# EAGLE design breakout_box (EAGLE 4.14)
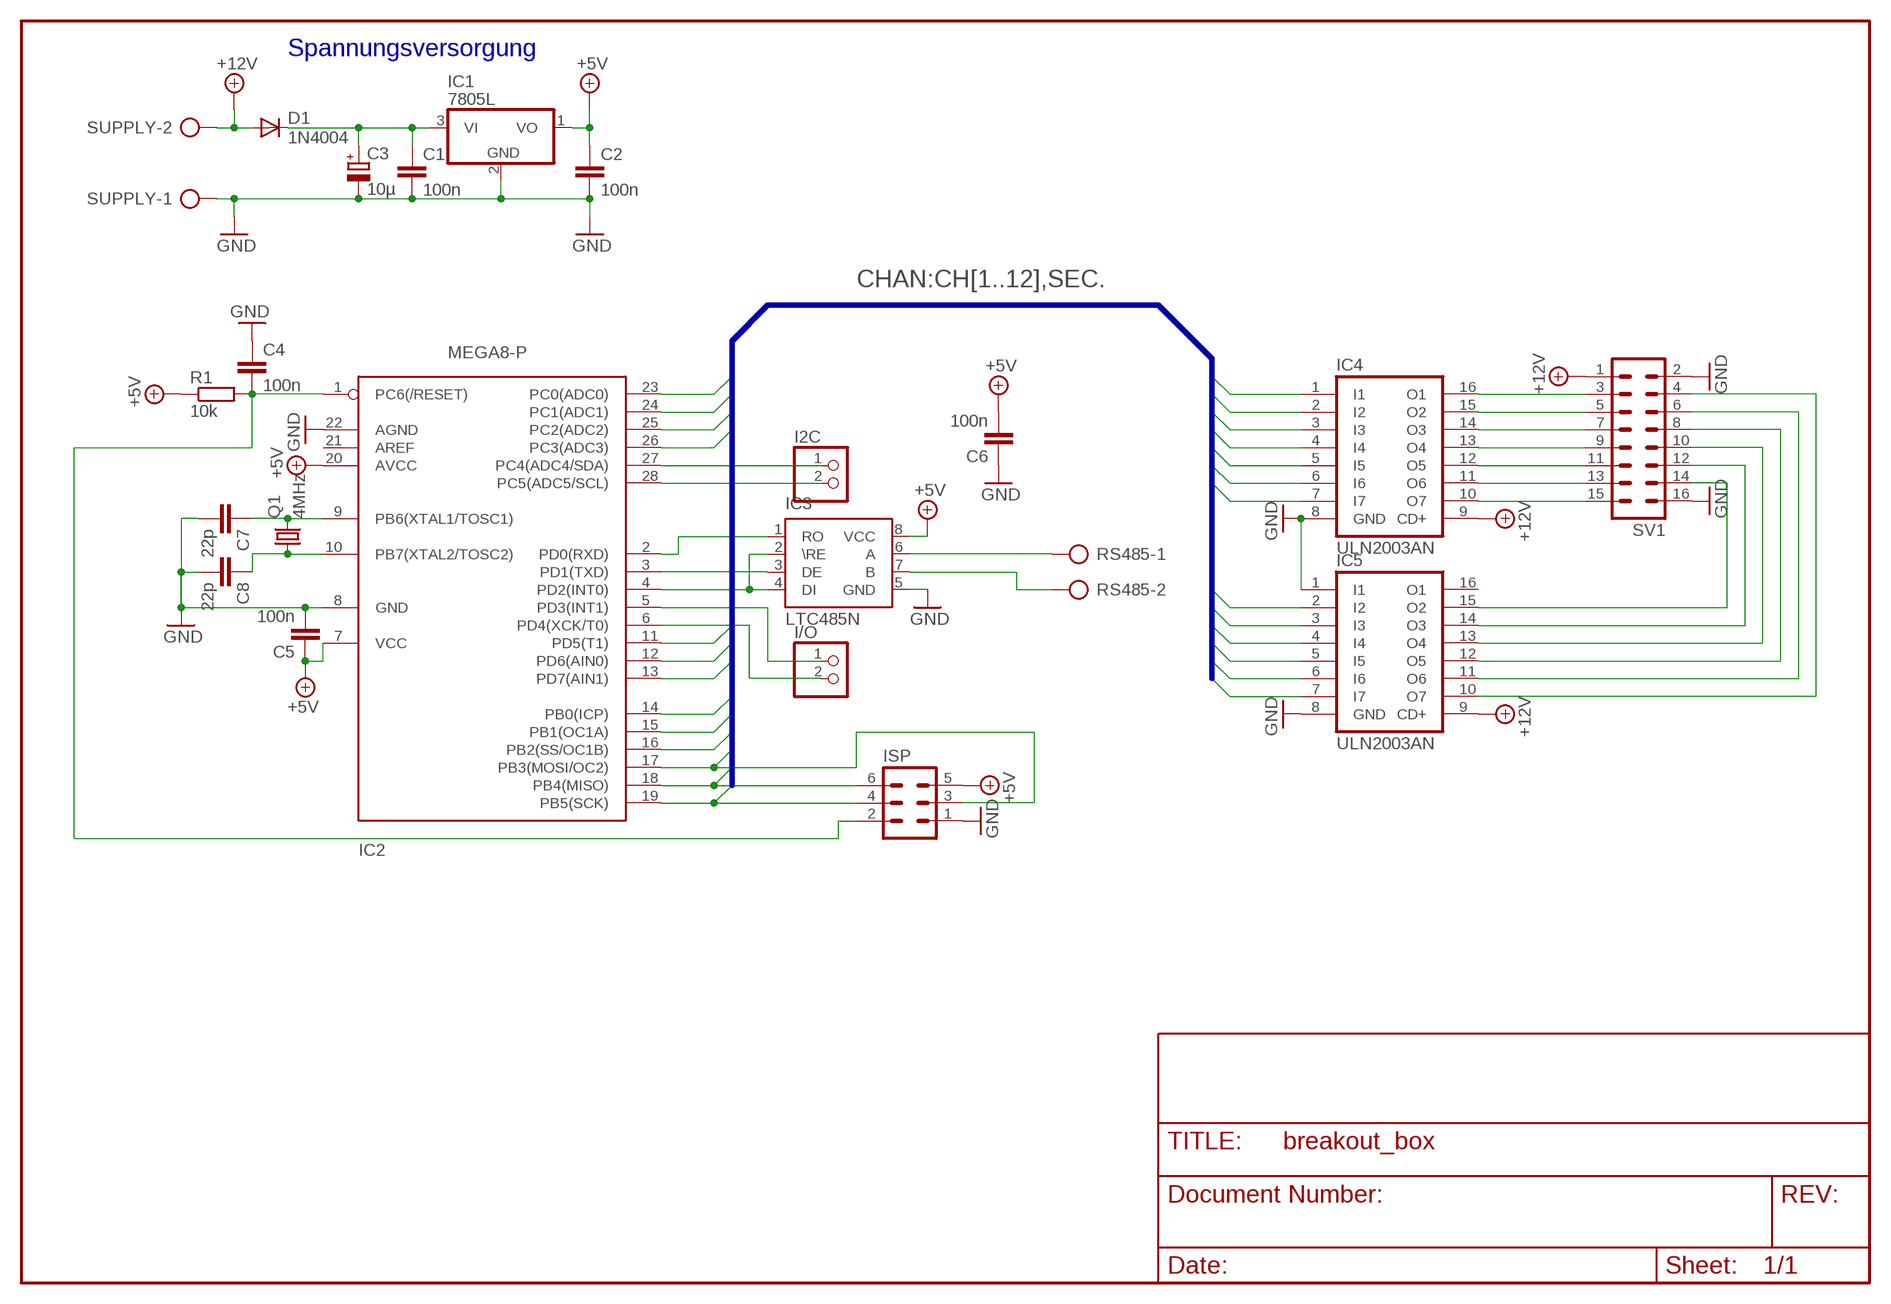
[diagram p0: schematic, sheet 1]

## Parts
C1  100n  C-EU025-024X044  [C025-024X044]
C2  100n  C-EU025-024X044  [C025-024X044]
C3  10µ  CPOL-EUE2-5  [E2-5]
C4  100n  C-EU025-024X044  [C025-024X044]
C5  100n  C-EU025-024X044  [C025-024X044]
C6  100n  C-EU025-024X044  [C025-024X044]
C7  22p  C-EU025-024X044  [C025-024X044]
C8  22p  C-EU025-024X044  [C025-024X044]
D1  1N4004  [DO41-10]
I2C  PINHD-1X2  [1X02]
I/O  PINHD-1X2  [1X02]
IC1  7805L  [TO92]
IC2  MEGA8-P  [DIL28-3]
IC3  LTC485N  [DIL08]
IC4  ULN2003AN  [DIL16]
IC5  ULN2003AN  [DIL16]
ISP  ML6  [ML6]
Q1  4MHz  CRYTALHC49U-V  [HC49U-V]
R1  10k  R-EU_0207/10  [0207/10]
RS485  AK500/2  [AK500/2]
SUPPLY  AK500/2  [AK500/2]
SV1  ML16  [ML16]

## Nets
+5V: C2.1 C5.1 C6.2 IC1.1(VO) IC2.7(VCC) IC2.20(AVCC) IC3.8(VCC) ISP.5 R1.1
+12V: D1.A IC4.9(CD+) IC5.9(CD+) SUPPLY.2 SV1.1
CH1: IC2.26(PC3(ADC3)) IC4.1(I1)
CH2: IC2.25(PC2(ADC2)) IC4.2(I2)
CH3: IC2.24(PC1(ADC1)) IC4.3(I3)
CH4: IC2.19(PB5(SCK)) IC4.4(I4) ISP.4
CH5: IC2.18(PB4(MISO)) IC4.5(I5) ISP.6
CH6: IC2.17(PB3(MOSI/OC2)) IC4.6(I6) ISP.3
CH7: IC2.16(PB2(SS/OC1B)) IC4.7(I7)
CH8: IC2.15(PB1(OC1A)) IC5.3(I3)
CH9: IC2.14(PB0(ICP)) IC5.4(I4)
CH10: IC2.13(PD7(AIN1)) IC5.5(I5)
CH11: IC2.12(PD6(AIN0)) IC5.6(I6)
CH12: IC2.11(PD5(T1)) IC5.7(I7)
GND: C1.2 C2.2 C3.- C4.1 C5.2 C6.1 C7.2 C8.2 IC1.2(GND) IC2.8(GND) IC2.22(AGND) IC3.5(GND) IC4.8(GND) IC5.1(I1) IC5.8(GND) ISP.1 SUPPLY.1 SV1.2 SV1.16
N$1: IC3.7(B) RS485.2
N$2: IC3.6(A) RS485.1
N$3: IC2.2(PD0(RXD)) IC3.1(RO)
N$4: IC2.3(PD1(TXD)) IC3.3(DE)
N$5: IC4.16(O1) SV1.3
N$6: I/O.1 IC2.5(PD3(INT1))
N$7: IC4.15(O2) SV1.5
N$8: I2C.1 IC2.27(PC4(ADC4/SDA))
N$9: I2C.2 IC2.28(PC5(ADC5/SCL))
N$10: C7.1 IC2.9(PB6(XTAL1/TOSC1)) Q1.2
N$11: C1.1 C3.+ D1.C IC1.3(VI)
N$12: IC4.14(O3) SV1.7
N$13: IC4.13(O4) SV1.9
N$14: IC4.12(O5) SV1.11
N$15: IC4.11(O6) SV1.13
N$16: IC4.10(O7) SV1.15
N$17: IC5.15(O2) SV1.14
N$18: I/O.2 IC2.6(PD4(XCK/T0))
N$19: IC5.14(O3) SV1.12
N$20: IC5.13(O4) SV1.10
N$21: IC5.12(O5) SV1.8
N$22: IC5.11(O6) SV1.6
N$23: IC5.10(O7) SV1.4
N$24: C8.1 IC2.10(PB7(XTAL2/TOSC2)) Q1.1
N$25: IC2.4(PD2(INT0)) IC3.2(\RE) IC3.4(DI)
RESET: C4.2 IC2.1(PC6(/RESET)) ISP.2 R1.2
SEC.: IC2.23(PC0(ADC0)) IC5.2(I2)
Unconnected: IC2.21(AREF) IC5.16(O1)

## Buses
CHAN:CH[1..12],SEC.

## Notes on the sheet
- Spannungsversorgung

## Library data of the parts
C1 C2 C4-C8 = rcl:C-EU: CAPACITOR, European symbol
C3 = rcl:CPOL-EU: POLARIZED CAPACITOR, European symbol
D1 = diode:1N4004: DIODE
I2C I/O = pinhead:PINHD-1X2: PIN HEADER
IC1 = linear:78*: Positive VOLTAGE REGULATOR Source: http://cache.national.com/ds/LM/LM78L05.pdf http://www.fairchildsemi.com/ds/LM/LM7805.pdf
IC2 = atmel:MEGA8-P: MICROCONTROLLER 8 Kbytes FLASH 1 kbytes SRAM 512 bytes EEPROM USART 4-channel 10 bit ADC 2-channel 8 bit ADC Source: avr.lbr
IC3 = linear-technology:LTC485: Low Power RS485 Interface Transceiver Source: http://www.linear.com/pc/downloadDocument.do?navId=H0,C1,C1007,C1017,P2064,D1718
IC4 IC5 = uln-udn:ULN2003A: DRIVER ARRAY
ISP = con-harting-ml:ML6: HARTING
Q1 = crystal:CRYTAL: CRYSTAL
R1 = rcl:R-EU_: RESISTOR, European symbol
RS485 SUPPLY = con-ptr500:AK500/2: CONNECTOR
SV1 = con-harting-ml:ML16: HARTING

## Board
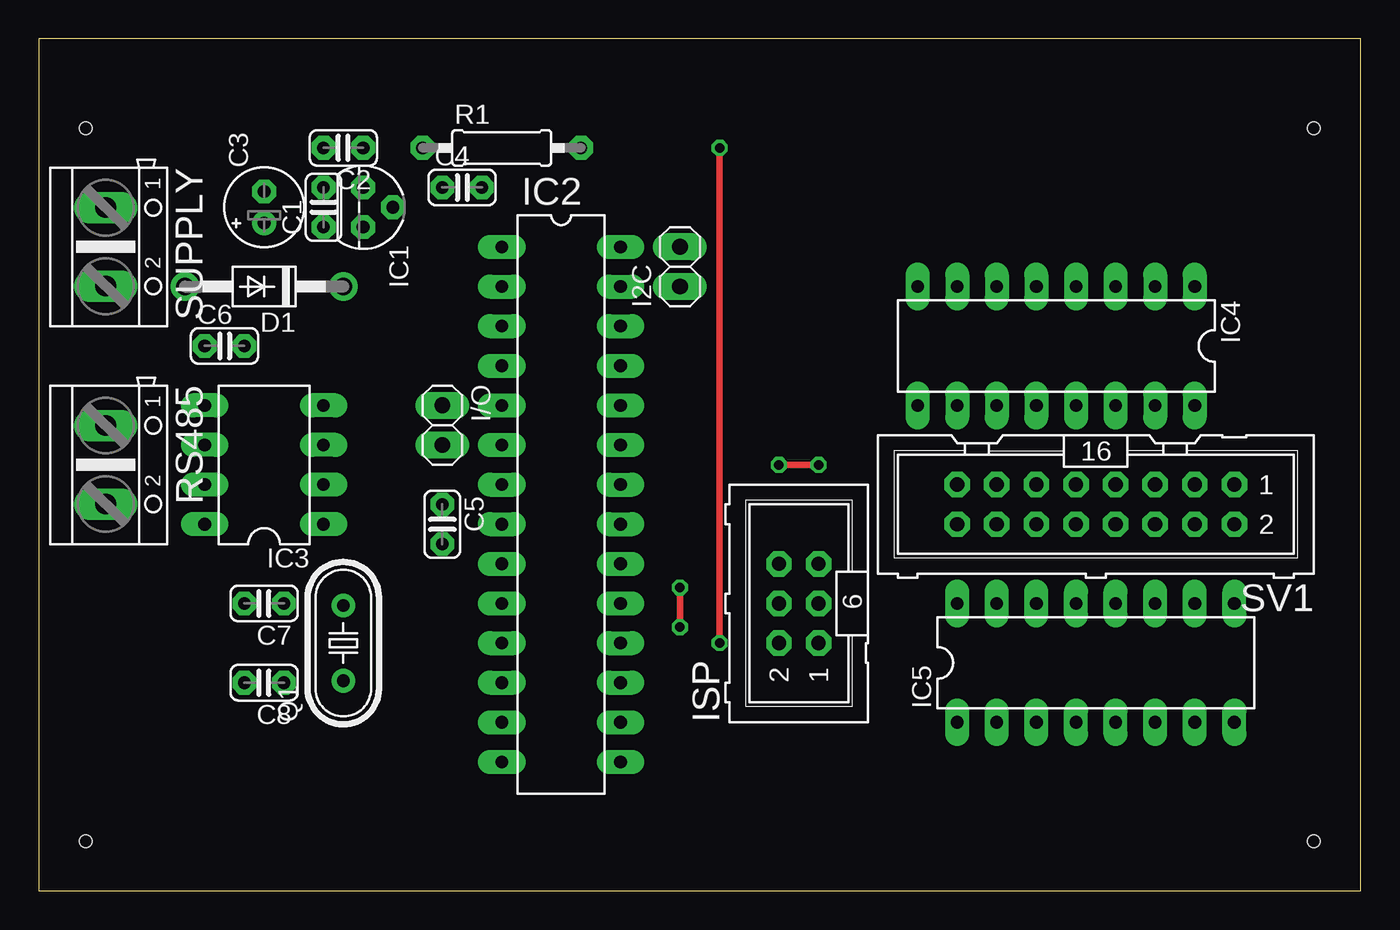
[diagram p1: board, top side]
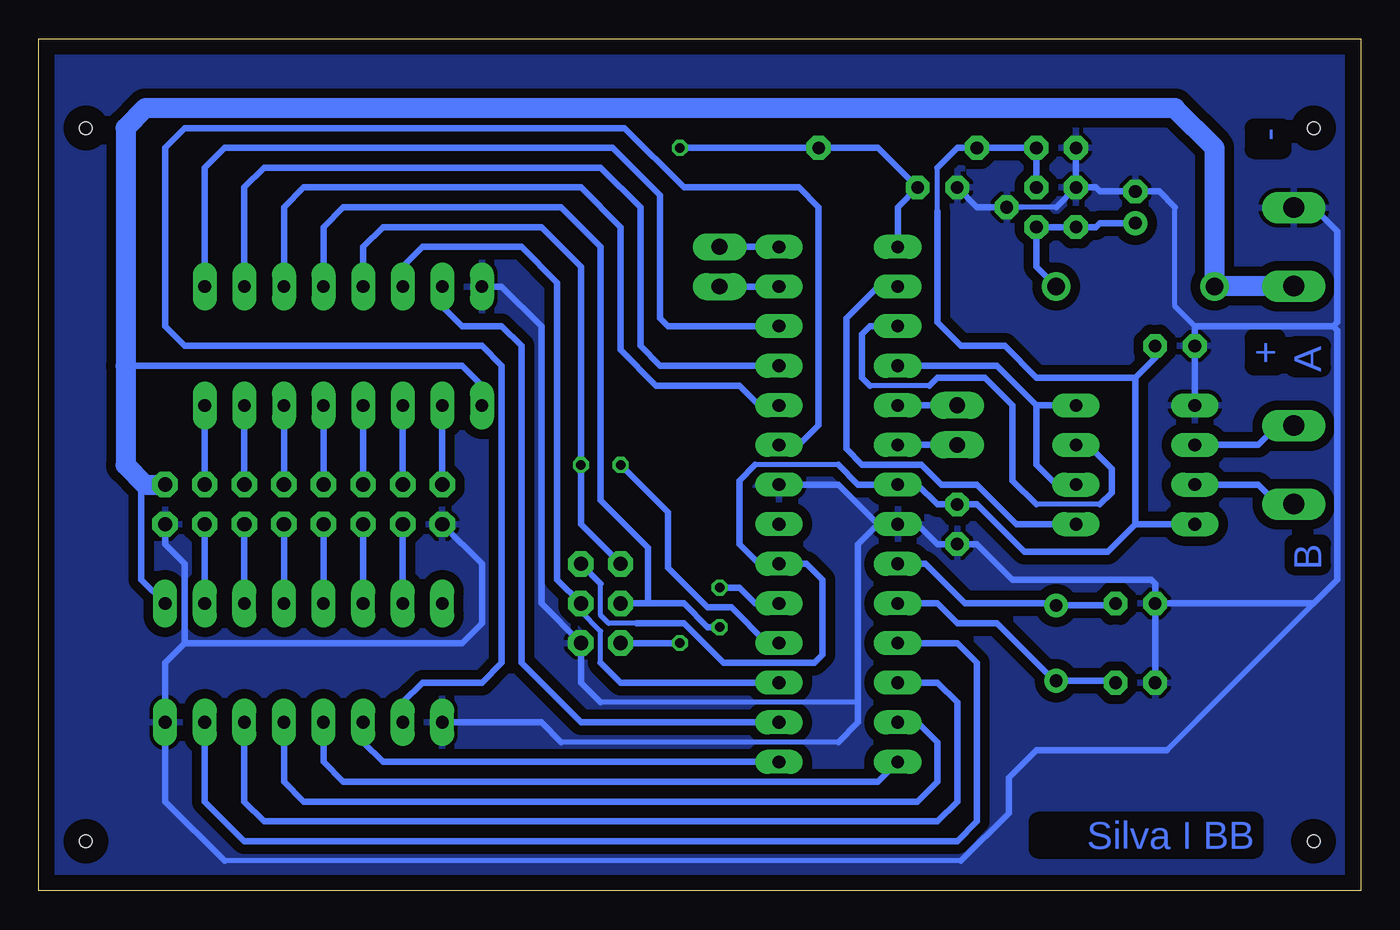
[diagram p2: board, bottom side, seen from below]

Size 84.76 x 54.6 mm. Coordinates in mm from the lower left corner, seen from the top.
Outline: 0,0 84.76,0 84.76,54.6 0,54.6 0,0
Copper layers (1*16): Top 0.035mm / dielectric 1.5mm / Bottom 0.035mm
Design rules "default": minimum track width 12mil, minimum drill 24mil, track to track 12mil, track to pad 12mil, pad to pad 12mil, via to via 12mil, smd to smd 8mil, copper to edge 40mil, drill to drill 8mil, minimum pad ring 14mil, minimum via ring 8mil, stop-mask expansion 4mil, vias tented up to drill 0mil, thermal gap 10mil
Holes 0.8 mm at 81.75,48.89 81.75,3.17 3.01,48.89 3.01,3.17

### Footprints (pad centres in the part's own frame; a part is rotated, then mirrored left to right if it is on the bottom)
C025-024X044 = drill 0.813 octagon: 1 -1.27,0; 2 1.27,0
E2-5 = drill 0.813 pad 1.27 round: + -1.016,0 | drill 0.813 pad 1.27 octagon: - 1.016,0
DO41-10 = drill 1.118 round: A 5.08,0; C -5.08,0
1X02 = drill 1.016 long: 1 -1.27,0; 2 1.27,0
TO92 = drill 0.813 octagon: 1 -1.27,0; 2 0,1.905; 3 1.27,0
DIL28-3 = drill 0.813 long: 1 -16.51,-3.81; 2 -13.97,-3.81; 3 -11.43,-3.81; 4 -8.89,-3.81; 5 -6.35,-3.81; 6 -3.81,-3.81; 7 -1.27,-3.81; 8 1.27,-3.81; 9 3.81,-3.81; 10 6.35,-3.81; 11 8.89,-3.81; 12 11.43,-3.81; 13 13.97,-3.81; 14 16.51,-3.81; 15 16.51,3.81; 16 13.97,3.81; 17 11.43,3.81; 18 8.89,3.81; 19 6.35,3.81; 20 3.81,3.81; 21 1.27,3.81; 22 -1.27,3.81; 23 -3.81,3.81; 24 -6.35,3.81; 25 -8.89,3.81; 26 -11.43,3.81; 27 -13.97,3.81; 28 -16.51,3.81
DIL08 = drill 0.813 long: 1 -3.81,-3.81; 2 -1.27,-3.81; 3 1.27,-3.81; 4 3.81,-3.81; 5 3.81,3.81; 6 1.27,3.81; 7 -1.27,3.81; 8 -3.81,3.81
DIL16 = drill 0.813 long: 1 -8.89,-3.81; 2 -6.35,-3.81; 3 -3.81,-3.81; 4 -1.27,-3.81; 5 1.27,-3.81; 6 3.81,-3.81; 7 6.35,-3.81; 8 8.89,-3.81; 9 8.89,3.81; 10 6.35,3.81; 11 3.81,3.81; 12 1.27,3.81; 13 -1.27,3.81; 14 -3.81,3.81; 15 -6.35,3.81; 16 -8.89,3.81
ML6 = drill 0.914 octagon: 1 -2.54,-1.27; 2 -2.54,1.27; 3 0,-1.27; 4 0,1.27; 5 2.54,-1.27; 6 2.54,1.27
HC49U-V = drill 0.813 round: 1 -2.413,0; 2 2.413,0
0207/10 = drill 0.813 octagon: 1 -5.08,0; 2 5.08,0
AK500/2 = drill 1.321 long: 1 -2.515,0; 2 2.515,0
ML16 = drill 0.914 octagon: 1 -8.89,-1.27; 2 -8.89,1.27; 3 -6.35,-1.27; 4 -6.35,1.27; 5 -3.81,-1.27; 6 -3.81,1.27; 7 -1.27,-1.27; 8 -1.27,1.27; 9 1.27,-1.27; 10 1.27,1.27; 11 3.81,-1.27; 12 3.81,1.27; 13 6.35,-1.27; 14 6.35,1.27; 15 8.89,-1.27; 16 8.89,1.27

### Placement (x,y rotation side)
C1  18.25,43.81 90 top
C2  19.52,47.62 180 top
C3  14.44,43.81 90 top
C4  27.14,45.08 0 top
C5  25.87,23.49 270 top
C6  11.9,34.92 0 top
C7  14.44,18.41 180 top
C8  14.44,13.33 180 top
D1  14.44,38.73 180 top
I2C  41.11,40 90 top
I/O  25.87,29.84 270 top
IC1  20.79,43.81 270 top
IC2  33.49,24.76 270 top
IC3  14.44,27.3 90 top
IC4  65.24,34.92 180 top
IC5  67.78,14.6 0 top
ISP  48.73,18.41 90 top
Q1  19.52,15.87 90 top
R1  29.68,47.62 0 top
RS485  4.28,27.3 270 top
SUPPLY  4.28,41.27 270 top
SV1  67.78,24.76 180 top

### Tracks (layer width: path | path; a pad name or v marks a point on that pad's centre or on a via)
+5V
  Bottom 0.305: 27.14,43.56 27.14,46.35 | IC3.8 11.9,23.49 | 33.49,27.3 38.82,27.3 | 48.73,19.68 48.73,17.65 48.22,17.14 46.44,17.14
  Bottom 0.406: 11.9,23.49 14.44,23.49 | 14.44,23.49 14.44,32.89 | IC1.1 C2.1 R1.1 25.87,47.62 27.14,46.35 | 14.44,32.89 20.79,32.89 22.82,34.92 25.62,34.92 27.14,36.44 27.14,43.56 | 14.44,23.49 16.22,21.71 21.55,21.71 24.6,24.76 C5.1 27.14,24.76 28.41,26.03 IC2.7 32.22,26.03 33.49,27.3 | 14.44,32.89 13.17,34.16 C6.2 | 38.82,27.3 39.84,26.28 39.84,22.22 38.57,20.95 IC2.20 35.52,20.95 34.51,19.93 34.51,15.11 35.01,14.6 40.86,14.6 43.4,17.14 46.44,17.14 | 48.73,19.68 ISP.5
+12V
  Bottom 0.406: IC4.9 56.35,32.38 57.62,33.65 79.21,33.65 | IC5.9 78.19,19.93 78.19,25.78 77.94,26.03
  Bottom 1.27: SV1.1 77.94,26.03 79.21,27.3 79.21,33.65 79.21,48.89 77.94,50.16 11.9,50.16 9.36,47.62 D1.A 9.34,38.75 SUPPLY.2
CH1
  Bottom 0.406: IC2.26 44.41,36.19 44.92,36.7 44.92,44.57 47.97,47.62 72.86,47.62 74.13,46.35 IC4.1
CH2
  Bottom 0.406: IC2.25 44.92,33.65 46.19,34.92 46.19,43.81 48.73,46.35 70.32,46.35 71.59,45.08 IC4.2
CH3
  Bottom 0.406: IC2.24 38.57,31.11 39.84,32.38 45.17,32.38 47.46,34.67 47.46,42.54 50,45.08 67.78,45.08 69.05,43.81 IC4.3
CH4  (via drill 0.61)
  Top 0.406: v41.11,19.43 v41.11,16.89
  Bottom 0.406: IC4.4 66.51,42.54 65.24,43.81 51.27,43.81 48.73,41.27 48.73,25.01 45.68,21.97 45.68,18.41 ISP.4 43.4,18.41 41.87,16.89 v41.11,16.89 | IC2.19 38.82,18.41 39.84,19.43 v41.11,19.43
CH5  (via drill 0.61)
  Top 0.406: v47.46,27.3 v50,27.3
  Bottom 0.406: ISP.6 50,23.49 v50,27.3 50,40 52.54,42.54 62.7,42.54 63.97,41.27 IC4.5 | IC2.18 38.06,15.87 40.35,18.16 41.87,18.16 44.41,20.7 44.41,24.25 v47.46,27.3
CH6
  Bottom 0.305: 48.73,14.6 48.73,16.63 50,17.9 ISP.3
  Bottom 0.406: IC2.17 47.46,13.33 48.73,14.6 | ISP.3 51.52,19.93 51.52,38.98 53.81,41.27 60.16,41.27 61.43,40 IC4.6
CH7
  Bottom 0.406: IC2.16 50,10.79 53.81,14.6 53.81,34.92 55.08,36.19 57.62,36.19 58.89,37.46 IC4.7
CH8
  Bottom 0.406: IC2.15 62.7,8.25 63.97,9.52 IC5.3
CH9
  Bottom 0.406: IC2.14 30.95,6.98 65.24,6.98 66.51,8.25 IC5.4
CH10
  Bottom 0.406: IC2.13 28.41,10.79 27.14,9.52 27.14,6.98 28.41,5.71 67.78,5.71 69.05,6.98 IC5.5
CH11
  Bottom 0.406: IC2.12 27.14,13.33 25.87,12.06 25.87,5.71 27.14,4.44 70.32,4.44 71.59,5.71 IC5.6
CH12
  Bottom 0.406: IC2.11 25.87,15.87 24.6,14.6 24.6,4.44 25.87,3.17 71.59,3.17 74.13,5.71 IC5.7
GND
  Bottom 0.305: 10.63,36.19 11.9,37.46 11.9,43.81 | 19.52,43.81 IC1.2 | 32.22,12.06 48.73,12.06 | 33.49,9.52 51.27,9.52 | 25.62,1.9 72.86,1.9 | 12.41,9.01 3.01,18.41
  Bottom 0.406: 75.4,15.87 76.67,14.6 IC5.8 76.67,5.71 72.86,1.9 | 75.4,15.87 75.4,20.95 76.67,22.22 SV1.2 | C7.2 C8.2 | IC4.8 55.08,38.73 52.54,36.19 52.54,18.41 ISP.1 50,13.33 48.73,12.06 | SV1.16 56.35,20.95 56.35,17.14 57.62,15.87 75.4,15.87 | SUPPLY.1 2.99,43.78 1.49,42.29 1.49,36.44 1.74,36.19 | 1.74,36.19 10.63,36.19 C6.1 IC3.5 | 11.9,43.81 12.92,44.83 C3.- 16.73,44.83 16.98,45.08 C1.2 | C1.2 C2.2 | C1.2 19.52,43.81 | IC1.2 24.6,43.81 C4.1 | 1.74,36.19 1.49,35.94 1.49,19.93 3.01,18.41 C7.2 | C7.2 13.17,19.68 13.42,19.93 22.31,19.93 24.6,22.22 C5.2 27.14,22.22 28.41,23.49 IC2.8 30.95,23.49 | 30.95,23.49 32.22,22.22 32.22,12.06 32.22,10.79 33.49,9.52 | IC5.1 52.54,10.79 51.27,9.52 | 25.62,1.9 22.57,4.95 22.57,7.23 20.79,9.01 12.41,9.01 | 30.95,23.49 33.49,26.03 IC2.22
  pour Bottom (isolate 0.61): 0.47,53.97 84.29,53.97 84.29,0.38 0.47,0.38
N$1
  Bottom 0.406: RS485.2 4.28,24.76 5.3,24.76 6.57,26.03 IC3.7
N$2
  Bottom 0.406: RS485.1 4.28,29.84 5.3,29.84 6.57,28.57 IC3.6
N$3
  Bottom 0.406: IC2.2 30.95,38.73 32.98,36.7 32.98,28.32 31.97,27.3 28.16,27.3 26.89,26.03 24.6,26.03 22.06,23.49 IC3.1
N$4
  Bottom 0.305: 16.73,24.76 20.79,24.76 | 27.65,32.38 31.46,32.38
  Bottom 0.406: IC3.3 17.49,28.57 15.96,27.05 15.96,25.52 16.73,24.76 | 20.79,24.76 22.31,26.28 22.31,31.11 24.09,32.89 27.14,32.89 27.65,32.38 | 31.46,32.38 31.97,32.89 31.97,35.68 31.46,36.19 IC2.3
N$5
  Bottom 0.406: SV1.3 IC4.16
N$6
  Bottom 0.406: I/O.1 IC2.5
N$7
  Bottom 0.406: SV1.5 IC4.15
N$8
  Bottom 0.406: IC2.27 I2C.1
N$9
  Bottom 0.406: IC2.28 I2C.2
N$10
  Bottom 0.406: IC2.9 27.9,20.95 25.36,18.41 19.52,18.41 Q1.2 15.84,18.28 C7.1
N$11
  Bottom 0.406: D1.C 20.79,40 IC1.3 C1.1 16.98,42.54 16.73,42.79 C3.+
N$12
  Bottom 0.406: SV1.7 IC4.14
N$13
  Bottom 0.406: SV1.9 IC4.13
N$14
  Bottom 0.406: SV1.11 IC4.12
N$15
  Bottom 0.406: SV1.13 IC4.11
N$16
  Bottom 0.406: SV1.15 IC4.10
N$17
  Bottom 0.406: IC5.15 SV1.14
N$18
  Bottom 0.406: I/O.2 IC2.6
N$19
  Bottom 0.406: IC5.14 SV1.12
N$20
  Bottom 0.406: IC5.13 SV1.10
N$21
  Bottom 0.406: IC5.12 SV1.8
N$22
  Bottom 0.406: IC5.11 SV1.6
N$23
  Bottom 0.406: IC5.10 SV1.4
N$24
  Bottom 0.406: IC2.10 27.14,18.41 25.87,17.14 23.33,17.14 19.65,13.46 Q1.1 15.84,13.46 C8.1
N$25
  Bottom 0.406: 20.79,31.11 IC3.4 | 20.79,31.11 20.79,27.3 19.52,26.03 IC3.2 | 20.79,31.11 23.33,33.65 IC2.4
RESET  (via drill 0.61)
  Top 0.406: v43.65,15.87 v43.65,47.62
  Bottom 0.406: IC2.1 29.68,43.81 C4.2 30.95,47.62 R1.2 v43.65,47.62 | v43.65,15.87 ISP.2
SEC.
  Bottom 0.406: IC2.23 36.03,28.57 34.76,29.84 34.76,43.81 36.03,45.08 43.4,45.08 47.21,48.89 75.4,48.89 76.67,47.62 76.67,36.19 75.4,34.92 56.35,34.92 55.08,33.65 55.08,14.6 56.35,13.33 60.16,13.33 61.43,12.06 IC5.2

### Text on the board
Bottom: - | A | + | B | Silva I BB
